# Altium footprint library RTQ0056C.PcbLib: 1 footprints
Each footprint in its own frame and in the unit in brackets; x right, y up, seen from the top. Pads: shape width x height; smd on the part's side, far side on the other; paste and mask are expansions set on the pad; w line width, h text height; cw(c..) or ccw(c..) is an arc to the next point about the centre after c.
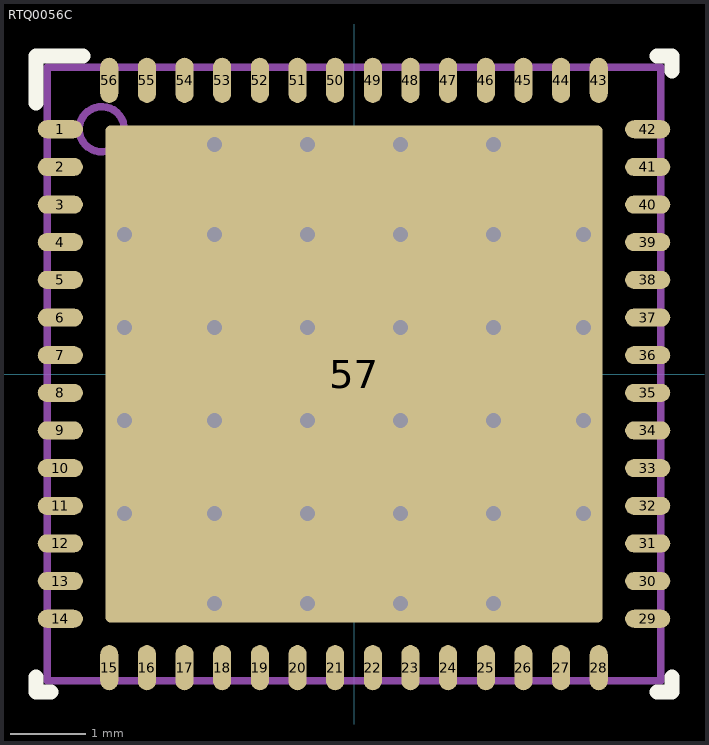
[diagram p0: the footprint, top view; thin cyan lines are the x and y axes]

## RTQ0056C [mm] "QFN, 56-Leads, Body 8x8mm, Pitch 0.5mm, Thermal Pad 6.6x6.6mm"
height 1
pads (57):
  rrect100% 0.6x0.24 smd: 1(-3.9,3.25) 2(-3.9,2.75) 3(-3.9,2.25) 4(-3.9,1.75) 5(-3.9,1.25) 6(-3.9,0.75) 7(-3.9,0.25) 8(-3.9,-0.25) 9(-3.9,-0.75) 10(-3.9,-1.25) 11(-3.9,-1.75) 12(-3.9,-2.25) 13(-3.9,-2.75) 14(-3.9,-3.25) 29(3.9,-3.25) 30(3.9,-2.75) 31(3.9,-2.25) 32(3.9,-1.75) 33(3.9,-1.25) 34(3.9,-0.75) 35(3.9,-0.25) 36(3.9,0.25) 37(3.9,0.75) 38(3.9,1.25) 39(3.9,1.75) 40(3.9,2.25) 41(3.9,2.75) 42(3.9,3.25)
  rrect100% 0.24x0.6 smd: 15(-3.25,-3.9) 16(-2.75,-3.9) 17(-2.25,-3.9) 18(-1.75,-3.9) 19(-1.25,-3.9) 20(-0.75,-3.9) 21(-0.25,-3.9) 22(0.25,-3.9) 23(0.75,-3.9) 24(1.25,-3.9) 25(1.75,-3.9) 26(2.25,-3.9) 27(2.75,-3.9) 28(3.25,-3.9) 43(3.25,3.9) 44(2.75,3.9) 45(2.25,3.9) 46(1.75,3.9) 47(1.25,3.9) 48(0.75,3.9) 49(0.25,3.9) 50(-0.25,3.9) 51(-0.75,3.9) 52(-1.25,3.9) 53(-1.75,3.9) 54(-2.25,3.9) 55(-2.75,3.9) 56(-3.25,3.9)
  rrect2% 6.6x6.6 smd paste-3.3: 57(0,0)
via 3.05,-0.618 diameter 0.5 hole 0.2
via 3.05,0.618 diameter 0.5 hole 0.2
via 0.618,-3.05 diameter 0.5 hole 0.2
via -0.618,-3.05 diameter 0.5 hole 0.2
via 1.854,-1.854 diameter 0.5 hole 0.2
via -1.854,-1.854 diameter 0.5 hole 0.2
via -3.05,-0.618 diameter 0.5 hole 0.2
via -3.05,0.618 diameter 0.5 hole 0.2
via 1.854,1.854 diameter 0.5 hole 0.2
via -1.854,1.854 diameter 0.5 hole 0.2
via -0.618,3.05 diameter 0.5 hole 0.2
via 0.618,3.05 diameter 0.5 hole 0.2
via -3.05,-1.854 diameter 0.5 hole 0.2
via -3.05,1.854 diameter 0.5 hole 0.2
via -1.854,3.05 diameter 0.5 hole 0.2
via -1.854,-3.05 diameter 0.5 hole 0.2
via -0.618,-1.854 diameter 0.5 hole 0.2
via -0.618,-0.618 diameter 0.5 hole 0.2
via -1.854,-0.618 diameter 0.5 hole 0.2
via -0.618,0.618 diameter 0.5 hole 0.2
via -1.854,0.618 diameter 0.5 hole 0.2
via -0.618,1.854 diameter 0.5 hole 0.2
via 0.618,1.854 diameter 0.5 hole 0.2
via 1.854,0.618 diameter 0.5 hole 0.2
via 0.618,0.618 diameter 0.5 hole 0.2
via 1.854,-0.618 diameter 0.5 hole 0.2
via 0.618,-0.618 diameter 0.5 hole 0.2
via 0.618,-1.854 diameter 0.5 hole 0.2
via 1.854,-3.05 diameter 0.5 hole 0.2
via 1.854,3.05 diameter 0.5 hole 0.2
via 3.05,1.854 diameter 0.5 hole 0.2
via 3.05,-1.854 diameter 0.5 hole 0.2
Top Overlay:
  lines w0.2: -4.225,-4.025 -4.225,-4.225 -4.025,-4.225 ; -4.225,3.6 -4.225,4.225 -3.6,4.225 ; 4.025,-4.225 4.225,-4.225 4.225,-4.025 ; 4.025,4.225 4.225,4.225 4.225,4.025
Top Paste:
  region: -0.718,-1.954 -1.754,-1.954 -1.754,-2.99 -0.718,-2.99
  region: -1.954,-1.954 -2.99,-1.954 -2.99,-2.99 -1.954,-2.99
  rectangle: 1.954,-2.99 2.99,-1.954
  rectangle: 0.718,-2.99 1.754,-1.954
  rectangle: -0.518,-2.99 0.518,-1.954
  region: -0.718,-0.718 -1.754,-0.718 -1.754,-1.754 -0.718,-1.754
  region: -1.954,-0.718 -2.99,-0.718 -2.99,-1.754 -1.954,-1.754
  rectangle: 1.954,-1.754 2.99,-0.718
  rectangle: 0.718,-1.754 1.754,-0.718
  rectangle: -0.518,-1.754 0.518,-0.718
  rectangle: -0.518,0.718 0.518,1.754
  rectangle: 0.718,0.718 1.754,1.754
  rectangle: 1.954,0.718 2.99,1.754
  region: -1.954,1.754 -2.99,1.754 -2.99,0.718 -1.954,0.718
  region: -0.718,1.754 -1.754,1.754 -1.754,0.718 -0.718,0.718
  rectangle: -0.518,1.954 0.518,2.99
  rectangle: 0.718,1.954 1.754,2.99
  rectangle: 1.954,1.954 2.99,2.99
  region: -1.954,2.99 -2.99,2.99 -2.99,1.954 -1.954,1.954
  region: -0.718,2.99 -1.754,2.99 -1.754,1.954 -0.718,1.954
  region: -0.718,0.518 -1.754,0.518 -1.754,-0.518 -0.718,-0.518
  region: -1.954,0.518 -2.99,0.518 -2.99,-0.518 -1.954,-0.518
  rectangle: 1.954,-0.518 2.99,0.518
  rectangle: 0.718,-0.518 1.754,0.518
  rectangle: -0.518,-0.518 0.518,0.518
M5 Assembly Top:
  circle w0.1: c-3.35,3.25 r0.3
  lines w0.1: -4.075,-4.075 4.075,-4.075 4.075,4.075 -4.075,4.075 -4.075,-4.075
  text ".Designator" at -1.524,-0.508 h1.02
3D body: height 1.01, standoff 0.5, extent -3.655,2.945 -3.045,3.555
3D body: height 1, standoff 0, extent -4.075,-4.075 4.075,4.075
